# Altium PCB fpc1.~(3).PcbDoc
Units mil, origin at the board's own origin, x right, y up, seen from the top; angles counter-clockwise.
Board outline 6000 x 4000 mil, 2 copper layers (Top Layer, Bottom Layer); 4 components, 1 nets, 0 pads, 0 vias.
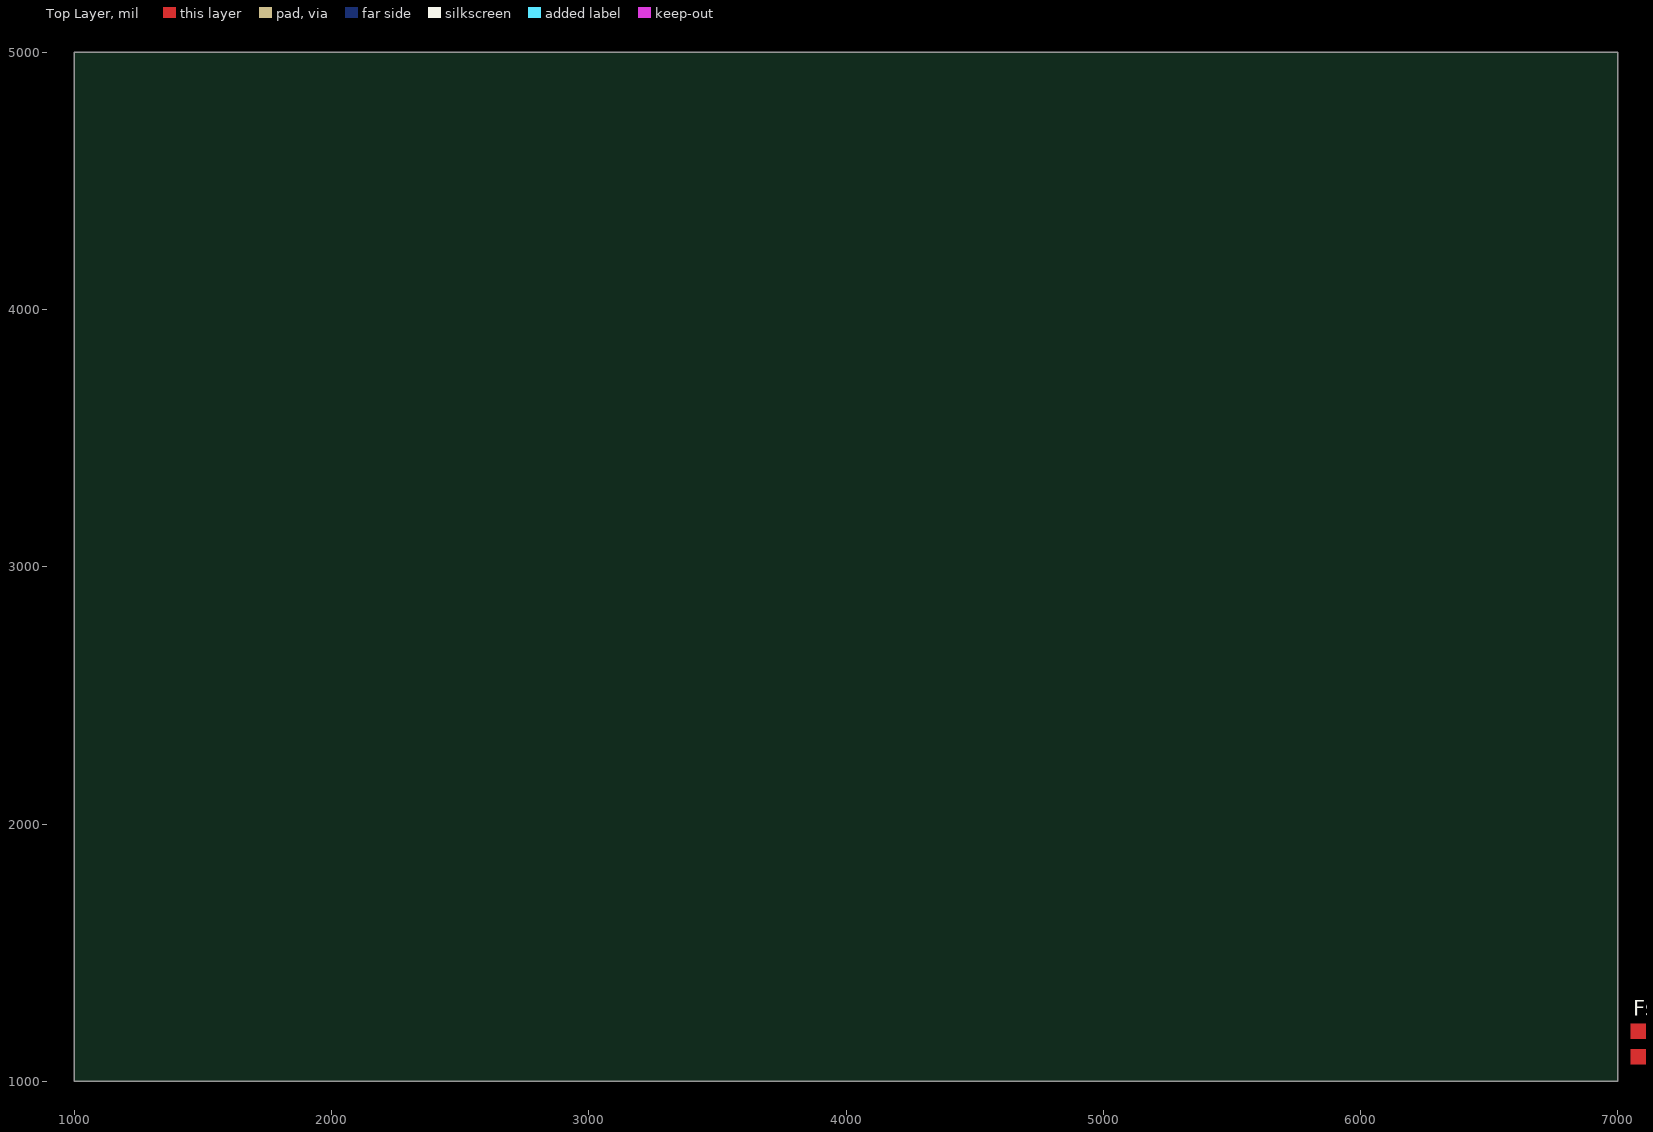
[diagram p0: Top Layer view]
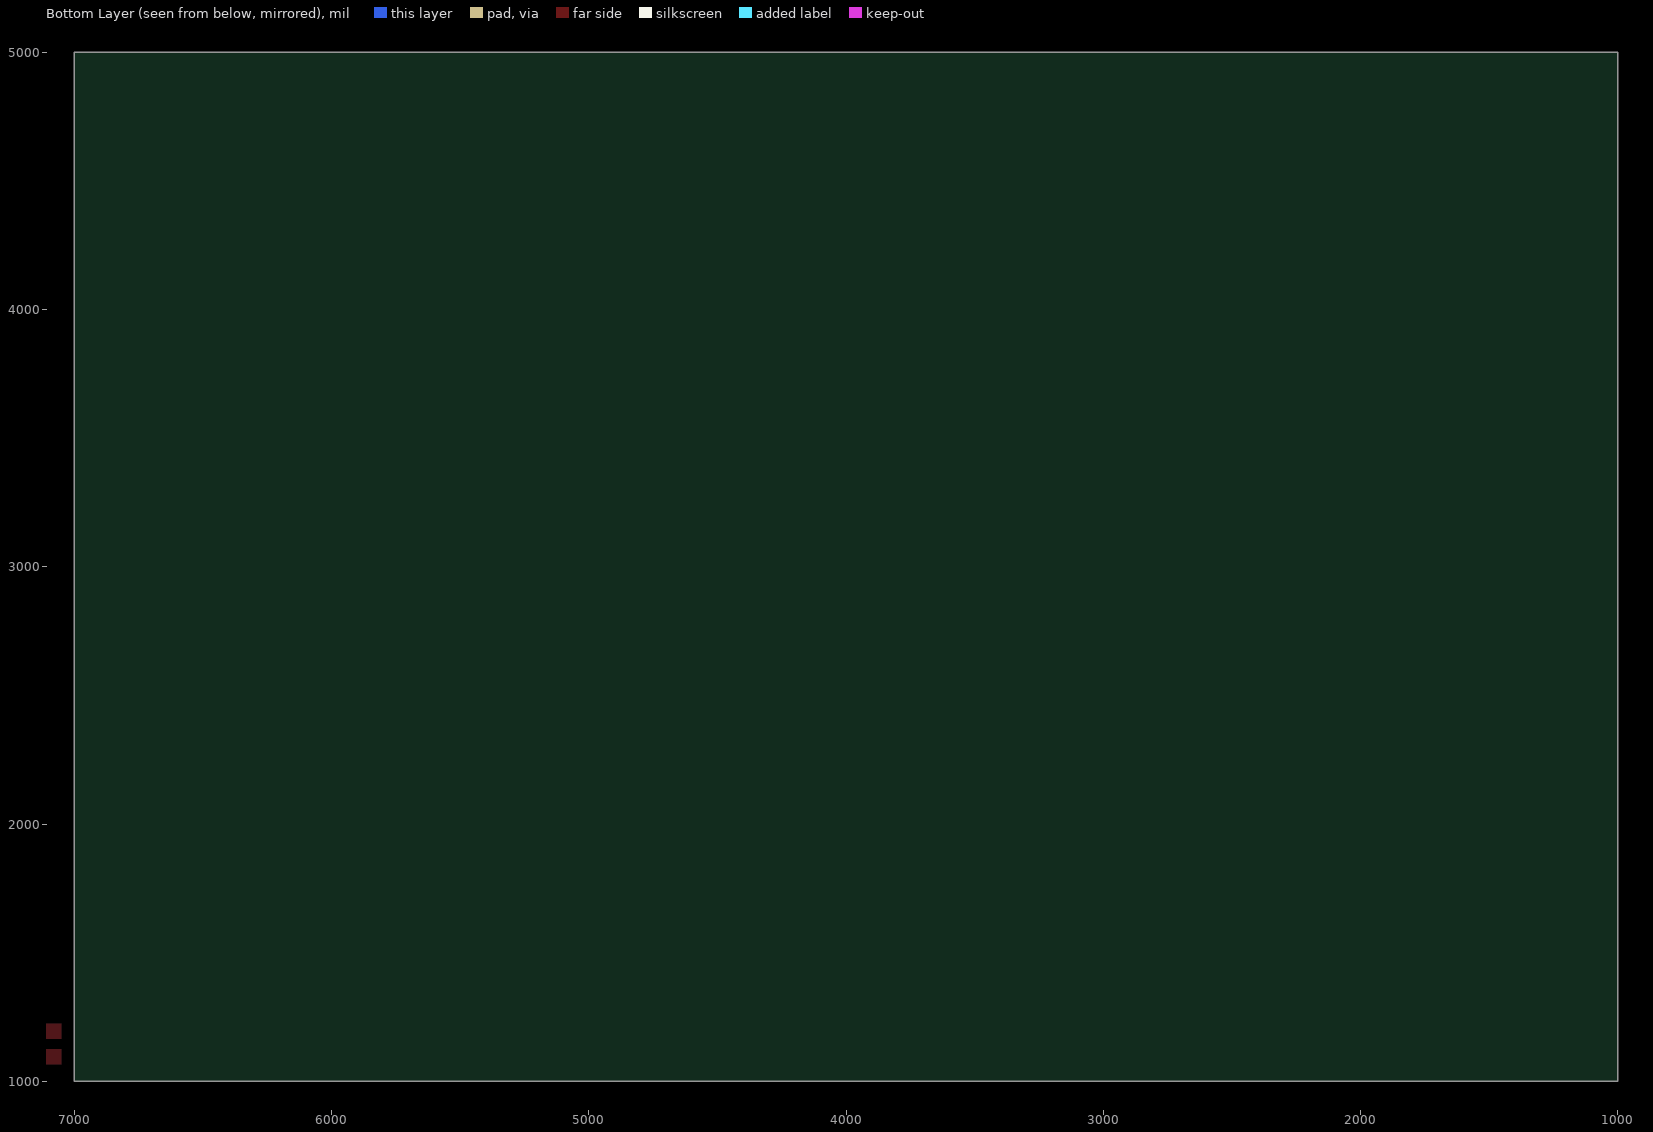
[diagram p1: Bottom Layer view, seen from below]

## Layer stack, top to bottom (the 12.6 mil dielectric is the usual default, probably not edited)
Top Solder: solder mask 0.4, Solder Resist, Dk 3.5
Top Layer: signal copper 1.4
Dielectric 1: dielectric 12.6, FR-4, Dk 4.8
Bottom Layer: signal copper 1.4
Bottom Solder: solder mask 0.4, Solder Resist, Dk 3.5

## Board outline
1000,1000 7000,1000 7000,5000 1000,5000

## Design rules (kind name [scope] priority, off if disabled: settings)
Clearance [All] p1: gap=10 ignorepadtopadclearanceinfootprint=FALSE except(0: Arc-Hole Track-Hole SMDPad-Hole THPad-Hole Via-Hole Fill-Hole Poly-Hole Region-Hole Text-Hole)
PolygonConnect [All] p1: connectstyle=Relief reliefconductorwidth=10 reliefentries=4 polygonreliefangle="90 Angle" airgapwidth=10
RoutingVias [All] p1: holewidth=28 width=50 viastyle="Through Hole" minholewidth=28 minwidth=50 maxholewidth=28 maxwidth=50
SolderMaskExpansion [All] p1: expansion=4 istentingtop=FALSE
Width [All] p1: maxlimit=10 minlimit=10 preferedwidth=10
30 further rules are at their usual default settings.

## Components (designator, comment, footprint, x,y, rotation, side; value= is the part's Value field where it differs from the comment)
Fs1 "ForceSensor" sensor_connector 7825,1195 r0 top
Fs2 "ForceSensor" sensor_connector 7545,1145 r90 top
Fs3 "ForceSensor" sensor_connector 7315,1145 r90 top
Fs4 "ForceSensor" sensor_connector 7080,1145 r90 top

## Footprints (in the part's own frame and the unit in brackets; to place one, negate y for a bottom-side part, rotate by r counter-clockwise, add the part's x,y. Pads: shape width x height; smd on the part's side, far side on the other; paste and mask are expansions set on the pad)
sensor_connector [mil]
  Top Layer region: -80,-30 -20,-30 -20,30 -80,30
  Top Layer region: 20,-30 80,-30 80,30 20,30

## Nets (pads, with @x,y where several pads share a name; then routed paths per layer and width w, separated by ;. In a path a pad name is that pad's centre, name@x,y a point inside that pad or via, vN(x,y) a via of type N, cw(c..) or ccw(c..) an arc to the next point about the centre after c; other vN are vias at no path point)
GND: 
